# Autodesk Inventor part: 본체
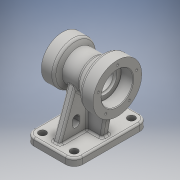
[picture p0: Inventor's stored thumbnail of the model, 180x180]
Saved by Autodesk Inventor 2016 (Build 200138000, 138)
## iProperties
Created: 2015-08
Part Number: 본체
Material: Generic
Document SubType Name: Modeling
Designer: Administrator
Density: 1 g/cm^3
Appearance: Default
Author: Administrator
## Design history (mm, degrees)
sketch "스케치1"
  geometry: L1 (45, 0)-(-45, 0); L2 (45, 0)-(45, 35); L3 (45, 35)-(25, 35); L4 (25, 35)-(19.804, 26); L5 (19.804, 26)-(-8.315, 26); L6 (-8.315, 26)-(-25, 40); L7 (-25, 40)-(-45, 40); L8 (-45, 40)-(-45, 0); 2 further points
  constraints: 16 end point, 2 coincident, 2 parallel, 2 perpendicular, 1 horizontal, 1 midpoint, 1 vertical
  dimensions: "d0" = 90 distance of L1.start L1.end; "d1" = 80 diameter of L7 L1; "d2" = 52 diameter of L5 L1; "d3" = 40 deg angle of L5 L6; "d4" = 20 distance from line of L6.end L8; "d5" = 20 distance of L2.end L3.end; "d6" = 60 deg angle of L4 L5; "d7" = 70 diameter of L3 L1
revolve "회전1" sketch "스케치1" stored, may be unused: angle "d8" = 90 deg
node "작업 평면1"
sketch "스케치2"
  geometry: L1 (-45, -61)-(35, -61); L2 (35, -61)-(35, 61); L3 (35, 61)-(-45, 61); L4 (-45, 61)-(-45, -61); L5 (-45, 35)-(-45, -35) reference; 4 further points
  constraints: 8 end point, 3 midpoint, 2 horizontal alignment, 2 parallel, 1 coincident, 1 horizontal, 1 perpendicular
  dimensions: "d10" = 122 distance of L3.end L1.start; "d11" = 80 distance of L2.end L3.end
extrude "돌출1" join sketch "스케치2" distance "d12" = 12; taper "d13" = 0 deg
sketch "스케치12"
  geometry: L1 (-11, -51)-(1, -51); L2 (1, -51)-(1, 51); L3 (1, 51)-(-11, 51); L4 (-11, 51)-(-11, -51); L5 (-45, -61)-(35, -61) reference; L6 (-45, 61)-(-45, -61) reference; L7 (35, 61)-(-45, 61) reference; L8 (35, -61)-(35, 61) reference; 5 further points
  constraints: 8 end point, 4 midpoint, 2 parallel, 1 horizontal, 1 horizontal alignment, 1 perpendicular, 1 vertical alignment
  dimensions: "d99" = 10 distance between parallel lines of L3 L7; "d100" = 12 distance of L2.end L3.end
extrude "돌출4" join sketch "스케치12" distance "d101" = 90; taper "d102" = 0 deg
sketch "스케치13"
  geometry: L1 (0, 102)-(-90, 102) reference; L2 (-71.185, 76.091)-(0, 102); L3 (0, 0)-(-90, 0) reference; L4 (-71.185, 25.909)-(0, 0); L5 (-90, 27.935)-(-90, 0) reference; L6 (-90, 0)-(-90, 27.935) reference; L7 (-90, 74.065)-(-90, 102) reference; L8 (-90, 102)-(-90, 74.065) reference; L9 (-90, 27.935)-(-90, 0) reference; L10 (0, 0)-(-90, 0); L11 (-90, 0)-(-90, 27.935); L12 (-90, 74.065)-(-90, 102); L13 (-90, 102)-(0, 102); A1 r 26 centre (-78, 51) between (-90, 27.935) and (-90, 74.065) reference; A2 r 26 centre (-78, 51) between (-90, 27.935) and (-71.185, 25.909); A3 r 26 centre (-78, 51) between (-71.185, 76.091) and (-90, 74.065); 1 further point
  constraints: 12 end point, 6 point on circle, 2 centre point, 1 coincident, 1 collinear, 1 horizontal, 1 perpendicular, 1 vertical
  dimensions: "d105" = 20 deg angle of L1 L2; "d106" = 20 deg angle of L3 L4
extrude "돌출5" cut sketch "스케치13" stored distance "d107" = 90; taper "d108" = 0 deg
sketch "스케치4"
  geometry: L1 (-45, -40)-(-25, -40) reference; L2 (-31.7, -40)-(-25, -78); L3 (-35, -78)-(45, -78) reference; L4 (-35, -90)-(-35, -78) reference; 1 further point
  constraints: 2 end point, 2 point on line
  dimensions: "d20" = 80 deg angle of L3 L2; "d21" = 10 distance from line of L2.end L4
feature "리브1" sketch "스케치4" dims "d22" = 1, "d23" = 12, "d24" = 0, "d25" = 0, "d26" = 1, "d27" = 1
sketch "스케치5"
  geometry: L1 (25, -35)-(45, -35) reference; L2 (35, -35)-(35, -78); L3 (-35, -78)-(45, -78) reference; L4 (45, -90)-(45, -78) reference; 1 further point
  constraints: 2 end point, 1 midpoint, 1 point on line, 1 vertical
  dimensions: "d28" = 10 distance between parallel lines of L2 L4
feature "리브2" sketch "스케치5" dims "d29" = 1, "d30" = 12, "d31" = 0, "d32" = 0, "d33" = 1, "d34" = 1
sketch "스케치6"
  geometry: L1 (-45, 0)-(45, 0); L2 (-45, -40)-(-45, 40) reference; L3 (45, -35)-(45, 35) reference; L4 (-45, 0)-(-45, 26); L5 (-45, 26)-(-25.3, 26); L6 (-25, 25.7)-(-25, 19); L7 (-25, 19)-(-25, 19); L8 (-22, 16)-(-22, 16); L9 (-22, 16)-(28, 16); L10 (28, 16)-(28, 19.7); L11 (28.3, 20)-(45, 20); L12 (45, 20)-(45, 0); A1 r 0.3 centre (-25.3, 25.7) between (-25, 25.7) and (-25.3, 26); A2 r 3 centre (-25, 16) between (-22, 16) and (-25, 19); A3 r 0.3 centre (28.3, 19.7) between (28.3, 20) and (28, 19.7); 2 further points
  constraints: 20 end point, 6 perpendicular, 6 point on circle, 6 tangent, 3 centre point, 3 midpoint, 2 coincident, 2 horizontal, 2 point on line, 1 collinear
  dimensions: "d35" = 40 diameter of L11 L1; "d36" = 32 diameter of L9 L1; "d37" = 17 distance between parallel lines of L3 L10; "d38" = 52 diameter of L5 L1; "d39" = 38 diameter of L7 L1; "d40" = 20 distance between parallel lines of L4 L6; "d41" = 3 distance between parallel lines of L6 L8; "d42" = 0.3 radius of A1; "d43" = 3 radius of A2; "d44" = 0.3 radius of A3
revolve "회전2" sketch "스케치6" stored, may be unused: angle "d45" = 90 deg
sketch "스케치14"
  geometry: L1 (-24, -36)-(-18, -36); L2 (-18, -24)-(-24, -24); L3 (0, -57)-(0, -12) reference; A1 r 6 centre (-24, -30) between (-24, -24) and (-24, -36); A2 r 6 centre (-18, -30) between (-18, -36) and (-18, -24); 1 further point
  constraints: 4 end point, 4 point on circle, 4 tangent, 2 centre point, 1 horizontal alignment
  dimensions: "d109" = 12 diameter of A1; "d110" = 12 diameter of A2; "d111" = 18 dimension on A2 A1; "d112" = 24 vertical distance of A1.centre point (-78, -6); "d113" = 18 distance from line of L3 A2.centre
extrude "돌출6" cut sketch "스케치14" stored distance "d114" = 90; taper "d115" = 0 deg
fillet "모깎기1" dims "d57" = 14
sketch "스케치8"
  geometry: A1 r 14 centre (-31, -47) between (-45, -47) and (-31, -61) reference; A2 r 14 centre (-31, 47) between (-31, 61) and (-45, 47) reference; A3 r 14 centre (21, 47) between (35, 47) and (21, 61) reference; A4 r 14 centre (21, -47) between (21, -61) and (35, -47) reference; 5 further points
  constraints: 4 coincident
hole "구멍1" sketch "스케치8" at (-31, -47), (-31, 47), (21, 47), (21, -47) diameter "d58" = 12; stored, may be unused: countersink angle "d62" = 90 deg, drill point angle "d64" = 118 deg; dims "d59" = 6, "d60" = 4, "d61" = 2, "d63" = 8
sketch "스케치9" dims "d65" = 66
  geometry: 3 further points
  constraints: 2 horizontal alignment, 1 coincident, 2 other
hole "구멍2" sketch "스케치9" at (-33, 0) diameter "d66" = 3.242; stored, may be unused: countersink angle "d70" = 90 deg, drill point angle "d72" = 118 deg; dims "d67" = 10, "d68" = 4, "d69" = 2, "d71" = 13
sketch "스케치10" dims "d76" = 54
  geometry: 3 further points
  constraints: 2 horizontal alignment, 1 coincident, 2 other
hole "구멍3" sketch "스케치10" at (27, 0) diameter "d77" = 3.242; stored, may be unused: countersink angle "d81" = 90 deg, drill point angle "d83" = 118 deg; dims "d78" = 10, "d79" = 4, "d80" = 2, "d82" = 13
chamfer "모따기1" distance "d87" = 1; stored, may be unused: second distance "d88" = 2, angle "d89" = 45 deg
fillet "모깎기2" dims "d90" = 5
fillet "모깎기3" dims "d91" = 3
fillet "모깎기4" dims "d92" = 3
fillet "모깎기5" dims "d93" = 3
fillet "모깎기6" dims "d94" = 3
sketch "스케치15"
  geometry: L1 (-16.928, -10.313)-(-16.928, -47.432) reference; L2 (39.072, -50.432)-(-12.928, -50.432) reference; 2 further points
  constraints: 1 other
  dimensions: "d118" = 16 distance from line of point (-0.928, -26.432) L1; "d119" = 24 distance from line of L2 point (-0.928, -26.432)
feature "엠보싱2" sketch "스케치15" dims "d0" = 90, "d1" = 80, "d2" = 52, "d3" = 40 deg, "d4" = 20, "d5" = 20, "d6" = 60 deg, "d7" = 70, "d120" = 0.5, "d121" = 0
fillet "모깎기7" dims "d122" = 3
fillet "모깎기8" dims "d123" = 3
fillet "모깎기9" dims "d124" = 3
fillet "모깎기10" dims "d125" = 3
node "솔리드1"
mirror "대칭1"
mirror "대칭2"
pattern_circular "원형 패턴1" dims angle "d74" = 360 deg
pattern_circular "원형 패턴2" dims angle "d85" = 360 deg
node "투영된 루프1"
node "투영된 루프2"
node "투영된 루프3"
